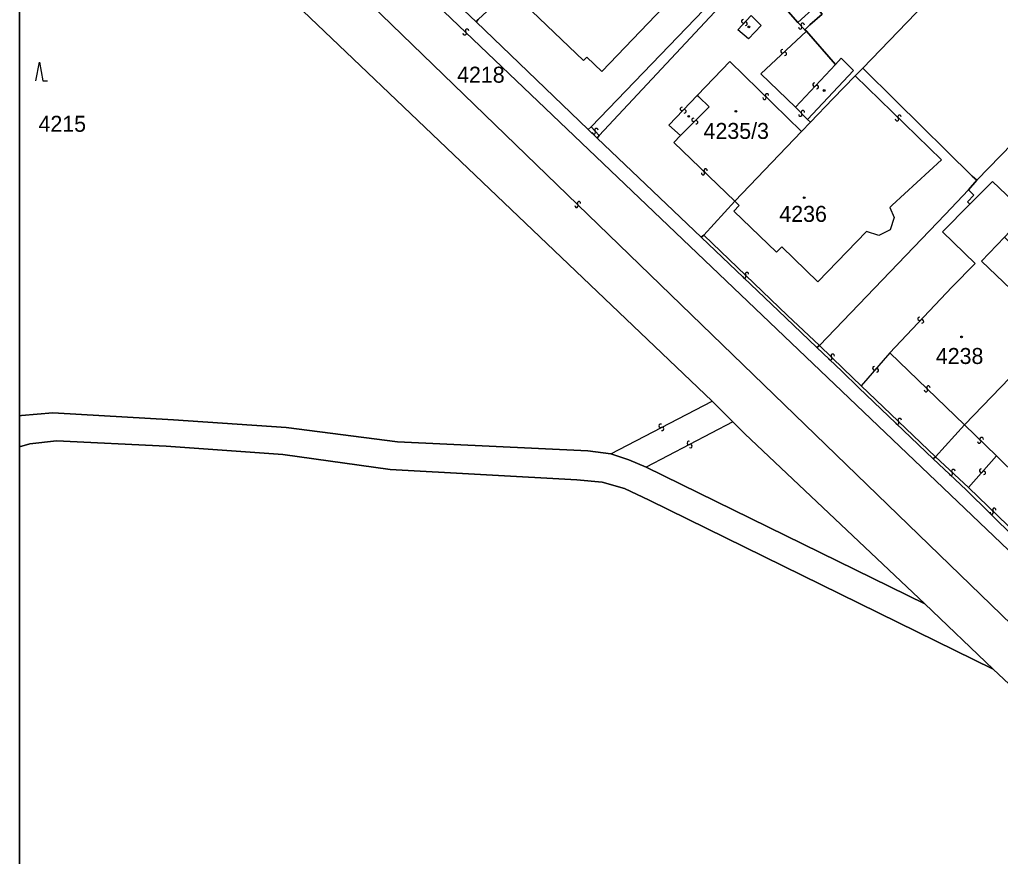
# Model space of a CAD drawing. Extents: x -598233 to -596890, y -1157848 to -1156431.
# Drawn here: x -598232.9 to -598128.6, y -1157143.3 to -1157054.3 of the extents above; entities that cross this region are included whole.
import ezdxf

# ---------------------------------------------------------------- set-up
doc = ezdxf.new("R2010")
doc.units = 0
for name, color, linetype in [('Level 1', 7, 'Continuous'), ('Level 13', 7, 'Continuous'), ('Level 3', 7, 'Continuous'), ('Level 4', 7, 'Continuous'), ('Level 5', 7, 'Continuous'), ('Level 60', 7, 'Continuous'), ('Vrstva 60', 7, 'Continuous'), ('zajmove_uzemi', 7, 'Continuous')]:
    doc.layers.add(name, color=color, linetype=linetype)

msp = doc.modelspace()

# ---------------------------------------------------------------- linework, layer by layer
at = {"layer": 'Level 1'}
for points in [[(-598159.23, -1157094.89), (-598230.25, -1157027.16), (-598232.89, -1157024.65)], [(-598184.32, -1157054.57), (-598196.28, -1157043.23)], [(-598172.99, -1157043.08), (-598163.59, -1157052.11), (-598170.97, -1157059.83), (-598172.56, -1157058.3), (-598172.9, -1157058.67), (-598180.74, -1157051.17)], [(-598129.11, -1157044.84), (-598143.19, -1157059.48)], [(-598107.13, -1157046.77), (-598131.06, -1157071.39)], [(-598155.51, -1157048.45), (-598172.08, -1157065.74)], [(-598154.89, -1157049.13), (-598171.23, -1157066.64)], [(-598150.09, -1157054.63), (-598154.89, -1157049.13)], [(-598149.35, -1157055.4), (-598148.81, -1157054.88), (-598147.53, -1157053.73), (-598148.21, -1157052.92), (-598150.09, -1157054.63)], [(-598184.11, -1157054.32), (-598184.32, -1157054.57)], [(-598172.39, -1157066), (-598184.32, -1157054.57)], [(-598149.19, -1157055.54), (-598149.35, -1157055.4)], [(-598146.08, -1157059.09), (-598149.19, -1157055.54)], [(-598149.06, -1157064.95), (-598144.17, -1157059.74), (-598145.5, -1157058.41), (-598146.08, -1157059.09)], [(-598143.19, -1157059.48), (-598144, -1157060.31)], [(-598143.19, -1157059.48), (-598139.69, -1157062.97), (-598131.54, -1157070.98), (-598131.06, -1157071.39)], [(-598148.77, -1157065.24), (-598146.37, -1157062.73), (-598144, -1157060.31)], [(-598148.77, -1157065.24), (-598149.73, -1157066.23)], [(-598148.77, -1157065.24), (-598149.06, -1157064.95)], [(-598172.08, -1157065.74), (-598172.39, -1157066)], [(-598171.46, -1157066.92), (-598172.39, -1157066)], [(-598149.73, -1157066.23), (-598156.81, -1157073.62)], [(-598171.23, -1157066.64), (-598171.46, -1157066.92)], [(-598160.37, -1157077.44), (-598171.46, -1157066.92)], [(-598131.06, -1157071.39), (-598131.93, -1157072.42)], [(-598131.8, -1157073.95), (-598129.39, -1157071.53), (-598125.76, -1157074.99), (-598128.13, -1157077.46)], [(-598131.93, -1157072.42), (-598134.44, -1157075.06), (-598147.81, -1157088.96)], [(-598131.93, -1157072.42), (-598131.37, -1157072.98), (-598132.05, -1157073.71), (-598131.8, -1157073.95)], [(-598156.81, -1157073.62), (-598160.11, -1157077.23)], [(-598160.11, -1157077.23), (-598160.37, -1157077.44)], [(-598148.09, -1157089.2), (-598151.37, -1157086.03), (-598160.37, -1157077.44)], [(-598147.81, -1157088.96), (-598148.09, -1157089.2)], [(-598135.7, -1157101.01), (-598143.6, -1157093.49), (-598145.41, -1157091.7), (-598148.09, -1157089.2)], [(-598124.02, -1157088.71), (-598125.63, -1157090.43), (-598132.37, -1157097.41)], [(-598159.23, -1157094.89), (-598157.01, -1157097.09)], [(-598232.89, -1157096.47), (-598232.68, -1157096.41), (-598229.34, -1157096.14), (-598216.51, -1157096.87), (-598204.52, -1157097.68), (-598192.69, -1157099.2), (-598172.45, -1157100.17), (-598170, -1157100.48)], [(-598157.01, -1157097.09), (-598155.74, -1157098.35), (-598136.59, -1157116.46)], [(-598132.37, -1157097.41), (-598135.45, -1157100.82)], [(-598232.89, -1157099.76), (-598231.79, -1157099.44), (-598228.95, -1157099.11), (-598217.31, -1157099.69), (-598204.89, -1157100.55), (-598193.47, -1157102.17), (-598173.62, -1157103.25), (-598170.91, -1157103.51), (-598168.54, -1157104.19), (-598165.93, -1157105.41), (-598129.31, -1157123.39)], [(-598170, -1157100.48), (-598168.09, -1157101.12), (-598166.23, -1157101.91)], [(-598135.45, -1157100.82), (-598135.7, -1157101.01)], [(-598127.04, -1157109.38), (-598132.19, -1157104.33), (-598135.7, -1157101.01)], [(-598166.23, -1157101.91), (-598136.59, -1157116.46)], [(-598136.59, -1157116.46), (-598129.31, -1157123.39)], [(-598129.31, -1157123.39), (-598117.4, -1157134.54)]]:
    msp.add_lwpolyline(points, dxfattribs=at)
at = {"layer": 'Level 13'}
for centre, start, end in [((-598155.91, -1157054.51), 84.726, 316.824), ((-598155.65, -1157054.77), 264.5116, 137.1016), ((-598149.59, -1157054.89), 351.2346, 223.3326), ((-598185.55, -1157055.77), 173.7072, 45.8052), ((-598185.29, -1157055.51), 353.4927, 226.0827), ((-598149.85, -1157055.15), 171.0201, 43.6101), ((-598151.74, -1157057.69), 80.4521, 313.0421), ((-598151.48, -1157057.96), 260.6666, 132.7646), ((-598148.34, -1157061.24), 84.2581, 316.3561), ((-598153.39, -1157062.38), 352.9445, 225.0425), ((-598148.08, -1157061.5), 264.0436, 136.6336), ((-598153.65, -1157062.64), 172.7301, 45.3201), ((-598162.43, -1157063.82), 83.381, 315.479), ((-598162.17, -1157064.08), 263.1666, 135.7566), ((-598149.83, -1157064.43), 171.7091, 43.8071), ((-598149.57, -1157064.17), 351.4946, 224.0847), ((-598161.19, -1157064.98), 82.3727, 314.4707), ((-598160.93, -1157065.24), 262.1583, 134.7483), ((-598139.55, -1157064.9), 172.95, 45.54), ((-598139.29, -1157064.64), 353.1645, 225.2625), ((-598171.8, -1157066.32), 170.7362, 42.8342), ((-598171.53, -1157066.06), 350.5217, 223.1117), ((-598160.18, -1157070.64), 173.4554, 45.5534), ((-598159.92, -1157070.38), 353.2409, 225.8309), ((-598173.39, -1157073.85), 353.311, 225.409), ((-598173.65, -1157074.11), 173.0966, 45.6866), ((-598155.78, -1157081.63), 173.4051, 45.9951), ((-598155.52, -1157081.37), 353.6195, 225.7175), ((-598137.15, -1157086.14), 83.9779, 316.0759), ((-598136.89, -1157086.4), 263.7635, 136.3535), ((-598146.65, -1157090.34), 172.9462, 45.5362), ((-598146.39, -1157090.08), 353.1606, 225.2586), ((-598141.97, -1157091.39), 86.3432, 318.9332), ((-598141.69, -1157091.63), 266.5577, 138.6556), ((-598136.21, -1157093.45), 353.1866, 225.7766), ((-598136.47, -1157093.71), 173.401, 45.499), ((-598164.7, -1157097.52), 64.8036, 296.9016), ((-598164.54, -1157097.84), 244.5891, 117.1791), ((-598139.53, -1157097.17), 173.456, 46.046), ((-598139.27, -1157096.91), 353.6705, 225.7685), ((-598161.7, -1157099.34), 64.7578, 297.3478), ((-598161.54, -1157099.66), 244.9722, 117.0702), ((-598130.81, -1157099.19), 173.0568, 45.1548), ((-598130.55, -1157098.93), 352.8424, 225.4324), ((-598133.82, -1157102.59), 174.4813, 46.5793), ((-598133.56, -1157102.33), 354.2669, 226.8569), ((-598130.6, -1157102.28), 86.1748, 318.2728), ((-598130.32, -1157102.52), 265.9603, 138.5503), ((-598129.47, -1157106.72), 173.3857, 45.4837), ((-598129.21, -1157106.46), 353.1713, 225.7613)]:
    msp.add_arc(centre, 0.184, start, end, dxfattribs=at)
at = {"layer": 'Level 3'}
msp.add_line((-598117.44, -1157120.53), (-598232.89, -1157010.34), dxfattribs=at)
for points in [[(-598232.89, -1157017.3), (-598226.27, -1157022.93), (-598120.77, -1157125.03), (-598117.44, -1157126.68)], [(-598155.34, -1157056.36), (-598156.48, -1157055.4), (-598155.08, -1157053.88), (-598154.02, -1157054.95), (-598155.34, -1157056.36)], [(-598150.09, -1157054.63), (-598149.35, -1157055.4)], [(-598149.19, -1157055.54), (-598154.03, -1157060.1), (-598150.34, -1157063.64)], [(-598160.77, -1157062.36), (-598157.32, -1157058.79), (-598149.73, -1157066.23)], [(-598150.34, -1157063.64), (-598146.08, -1157059.09)], [(-598144, -1157060.31), (-598134.83, -1157069.23), (-598140.06, -1157074.06), (-598140.31, -1157074.31), (-598139.84, -1157075.38), (-598140.28, -1157076.67), (-598141.48, -1157077.28), (-598142.79, -1157076.86), (-598147.99, -1157082.2), (-598151.81, -1157078.48), (-598152.38, -1157079.05), (-598156.9, -1157074.69), (-598156.34, -1157074.08), (-598156.81, -1157073.62)], [(-598162.59, -1157066.64), (-598163.84, -1157065.54), (-598160.77, -1157062.36)], [(-598162.59, -1157066.64), (-598159.53, -1157063.58), (-598160.64, -1157062.55), (-598160.77, -1157062.36)], [(-598149.06, -1157064.95), (-598150.34, -1157063.64)], [(-598171.23, -1157066.64), (-598172.08, -1157065.74)], [(-598156.81, -1157073.62), (-598163.28, -1157067.39), (-598162.59, -1157066.64)], [(-598140.31, -1157089.75), (-598133.72, -1157082.78), (-598131.23, -1157080.25), (-598134.72, -1157076.88), (-598131.8, -1157073.95)], [(-598160.11, -1157077.23), (-598151.19, -1157085.77), (-598147.81, -1157088.96)], [(-598122.79, -1157087.4), (-598130.58, -1157080.02), (-598128.13, -1157077.46)], [(-598147.81, -1157088.96), (-598145.23, -1157091.47), (-598143.35, -1157093.27)], [(-598140.31, -1157089.75), (-598143.35, -1157093.27)], [(-598132.37, -1157097.41), (-598140.31, -1157089.75)], [(-598143.35, -1157093.27), (-598135.45, -1157100.82)], [(-598170, -1157100.48), (-598159.23, -1157094.89)], [(-598117.55, -1157094.91), (-598122.09, -1157099.76), (-598122.77, -1157098.9), (-598126.59, -1157103.05), (-598128.98, -1157100.72)], [(-598157.01, -1157097.09), (-598166.23, -1157101.91)], [(-598128.98, -1157100.72), (-598132.37, -1157097.41)], [(-598131.93, -1157104.09), (-598135.45, -1157100.82)], [(-598131.93, -1157104.09), (-598128.98, -1157100.72)], [(-598126.75, -1157109.09), (-598131.93, -1157104.09)]]:
    msp.add_lwpolyline(points, dxfattribs=at)
at = {"layer": 'Level 5'}
msp.add_lwpolyline([(-598231.16, -1157060.85), (-598230.78, -1157058.85), (-598230.41, -1157060.85), (-598229.91, -1157060.85)], dxfattribs=at)
for centre, radius in [((-598155.31, -1157055.1), 0.09), ((-598155.31, -1157055.1), 0.0521), ((-598147.3, -1157061.86), 0.09), ((-598147.3, -1157061.86), 0.0521), ((-598156.69, -1157064.07), 0.09), ((-598156.69, -1157064.07), 0.0521), ((-598161.71, -1157064.61), 0.09), ((-598161.71, -1157064.61), 0.0521), ((-598149.42, -1157073.26), 0.09), ((-598149.42, -1157073.26), 0.0521), ((-598132.69, -1157088.06), 0.09), ((-598132.69, -1157088.06), 0.0521)]:
    msp.add_circle(centre, radius, dxfattribs=at)
at = {"layer": 'Level 60'}
for points in [[(-598170.52, -1157039.93), (-598175.51, -1157034.6), (-598176.86, -1157035.92), (-598178.45, -1157034.38), (-598178.73, -1157034.7), (-598179.5, -1157035.47), (-598181.82, -1157037.78), (-598183, -1157036.67), (-598186.42, -1157040.24), (-598185.27, -1157041.33), (-598187.95, -1157044.29), (-598180.74, -1157051.17), (-598184.11, -1157054.32), (-598184.32, -1157054.57), (-598196.28, -1157043.23), (-598196.05, -1157042.96), (-598180.92, -1157027.21), (-598179.15, -1157025.42), (-598173.93, -1157020.14), (-598164.13, -1157010.24), (-598153.32, -1157022.66), (-598162.98, -1157032.36), (-598164.84, -1157034.23), (-598167.89, -1157037.39)], [(-598138.82, -1157032.43), (-598154.89, -1157049.13), (-598171.23, -1157066.64), (-598171.46, -1157066.92), (-598172.39, -1157066), (-598172.08, -1157065.74), (-598155.51, -1157048.45), (-598153.3, -1157046.22), (-598151.44, -1157044.3), (-598133.54, -1157025.78), (-598128.72, -1157020.8), (-598124.4, -1157016.33), (-598115.98, -1157031.27), (-598129.11, -1157044.84)], [(-598143.19, -1157059.48), (-598129.11, -1157044.84), (-598115.98, -1157031.27), (-598109.57, -1157042.5), (-598107.13, -1157046.77), (-598131.06, -1157071.39), (-598131.54, -1157070.98), (-598139.69, -1157062.97)], [(-598154.89, -1157049.13), (-598138.82, -1157032.43), (-598129.11, -1157044.84), (-598143.19, -1157059.48), (-598144, -1157060.31), (-598146.37, -1157062.73), (-598148.77, -1157065.24), (-598149.06, -1157064.95), (-598144.17, -1157059.74), (-598145.5, -1157058.41), (-598146.08, -1157059.09), (-598149.19, -1157055.54), (-598149.35, -1157055.4), (-598148.81, -1157054.88), (-598147.53, -1157053.73), (-598148.21, -1157052.92), (-598150.09, -1157054.63)], [(-598184.11, -1157054.32), (-598180.74, -1157051.17), (-598172.9, -1157058.67), (-598172.56, -1157058.3), (-598170.97, -1157059.83), (-598163.59, -1157052.11), (-598172.99, -1157043.08), (-598170.74, -1157040.17), (-598170.52, -1157039.93), (-598167.89, -1157037.39), (-598164.84, -1157034.23), (-598161.43, -1157037.74), (-598156.32, -1157043.16), (-598155.48, -1157043.96), (-598153.3, -1157046.22), (-598155.51, -1157048.45), (-598172.08, -1157065.74), (-598172.39, -1157066), (-598184.32, -1157054.57)], [(-598180.74, -1157051.17), (-598172.99, -1157043.08), (-598163.59, -1157052.11), (-598170.97, -1157059.83), (-598172.56, -1157058.3), (-598172.9, -1157058.67)], [(-598131.93, -1157072.42), (-598131.06, -1157071.39), (-598107.13, -1157046.77), (-598106.45, -1157047.94), (-598098.39, -1157061.95), (-598101.09, -1157064.98), (-598105.4, -1157069.5), (-598120.39, -1157084.83), (-598121.14, -1157084.17), (-598121.86, -1157083.46), (-598128.13, -1157077.46), (-598125.76, -1157074.99), (-598129.39, -1157071.53), (-598131.8, -1157073.95), (-598132.05, -1157073.71), (-598131.37, -1157072.98)], [(-598149.06, -1157064.95), (-598148.77, -1157065.24), (-598149.73, -1157066.23), (-598156.81, -1157073.62), (-598160.11, -1157077.23), (-598160.37, -1157077.44), (-598171.46, -1157066.92), (-598171.23, -1157066.64), (-598154.89, -1157049.13), (-598150.09, -1157054.63), (-598148.21, -1157052.92), (-598147.53, -1157053.73), (-598148.81, -1157054.88), (-598149.35, -1157055.4), (-598149.19, -1157055.54), (-598146.08, -1157059.09), (-598145.5, -1157058.41), (-598144.17, -1157059.74)], [(-598148.77, -1157065.24), (-598146.37, -1157062.73), (-598144, -1157060.31), (-598143.19, -1157059.48), (-598139.69, -1157062.97), (-598131.54, -1157070.98), (-598131.06, -1157071.39), (-598131.93, -1157072.42), (-598134.44, -1157075.06), (-598147.81, -1157088.96), (-598148.09, -1157089.2), (-598151.37, -1157086.03), (-598160.37, -1157077.44), (-598160.11, -1157077.23), (-598156.81, -1157073.62), (-598149.73, -1157066.23)], [(-598134.44, -1157075.06), (-598131.93, -1157072.42), (-598131.37, -1157072.98), (-598132.05, -1157073.71), (-598131.8, -1157073.95), (-598129.39, -1157071.53), (-598125.76, -1157074.99), (-598128.13, -1157077.46), (-598121.86, -1157083.46), (-598121.14, -1157084.17), (-598120.39, -1157084.83), (-598120.83, -1157085.36), (-598121.73, -1157086.26), (-598122.79, -1157087.4), (-598124.02, -1157088.71), (-598125.63, -1157090.43), (-598132.37, -1157097.41), (-598135.45, -1157100.82), (-598135.7, -1157101.01), (-598143.6, -1157093.49), (-598145.41, -1157091.7), (-598148.09, -1157089.2), (-598147.81, -1157088.96)], [(-598121.73, -1157086.26), (-598120.83, -1157085.36), (-598119.23, -1157086.95), (-598114.31, -1157091.62), (-598116.02, -1157093.41), (-598115.04, -1157094.3), (-598113.88, -1157095.34), (-598123.68, -1157105.73), (-598126.75, -1157109.09), (-598127.04, -1157109.38), (-598132.19, -1157104.33), (-598135.7, -1157101.01), (-598135.45, -1157100.82), (-598132.37, -1157097.41), (-598125.63, -1157090.43), (-598124.02, -1157088.71), (-598122.79, -1157087.4)]]:
    msp.add_lwpolyline(points, close=True, dxfattribs=at)
at = {"layer": 'Vrstva 60'}
for points in [[(-598232.89, -1156430.86), (-598232.89, -1157835.58)], [(-598230.25, -1157027.16), (-598159.23, -1157094.89), (-598157.01, -1157097.09), (-598155.74, -1157098.35), (-598136.59, -1157116.46), (-598129.31, -1157123.39), (-598117.4, -1157134.54), (-598117.42, -1157133.54), (-598117.44, -1157130.35), (-598117.44, -1157118.61), (-598127.04, -1157109.38), (-598132.19, -1157104.33), (-598135.7, -1157101.01), (-598143.6, -1157093.49), (-598145.41, -1157091.7), (-598148.09, -1157089.2), (-598151.37, -1157086.03), (-598160.37, -1157077.44), (-598171.46, -1157066.92), (-598172.39, -1157066), (-598184.32, -1157054.57), (-598196.28, -1157043.23)], [(-598009.87, -1157147.41), (-598011.65, -1157136.39), (-598017.09, -1157116.49), (-598022.5, -1157094.64), (-598023.35, -1157090.35), (-598117.4, -1157134.54), (-598129.31, -1157123.39), (-598165.93, -1157105.41), (-598168.54, -1157104.19), (-598170.91, -1157103.51), (-598173.62, -1157103.25), (-598193.47, -1157102.17), (-598204.89, -1157100.55), (-598217.31, -1157099.69), (-598228.95, -1157099.11), (-598231.79, -1157099.44), (-598232.89, -1157099.76), (-598232.89, -1157171.98)]]:
    msp.add_lwpolyline(points, dxfattribs=at)
for points in [[(-598232.89, -1157024.65), (-598232.89, -1157096.47), (-598232.68, -1157096.41), (-598229.34, -1157096.14), (-598216.51, -1157096.87), (-598204.52, -1157097.68), (-598192.69, -1157099.2), (-598172.45, -1157100.17), (-598170, -1157100.48), (-598168.09, -1157101.12), (-598166.23, -1157101.91), (-598136.59, -1157116.46), (-598155.74, -1157098.35), (-598157.01, -1157097.09), (-598159.23, -1157094.89), (-598230.25, -1157027.16)], [(-598232.89, -1157096.47), (-598232.89, -1157099.76), (-598231.79, -1157099.44), (-598228.95, -1157099.11), (-598217.31, -1157099.69), (-598204.89, -1157100.55), (-598193.47, -1157102.17), (-598173.62, -1157103.25), (-598170.91, -1157103.51), (-598168.54, -1157104.19), (-598165.93, -1157105.41), (-598129.31, -1157123.39), (-598136.59, -1157116.46), (-598166.23, -1157101.91), (-598168.09, -1157101.12), (-598170, -1157100.48), (-598172.45, -1157100.17), (-598192.69, -1157099.2), (-598204.52, -1157097.68), (-598216.51, -1157096.87), (-598229.34, -1157096.14), (-598232.68, -1157096.41)]]:
    msp.add_lwpolyline(points, close=True, dxfattribs=at)
at = {"layer": 'zajmove_uzemi'}
msp.add_lwpolyline([(-598232.89, -1156430.86), (-596890.46, -1156430.86), (-596890.46, -1157848.46), (-598232.89, -1157848.46)], close=True, dxfattribs=at)

# ---------------------------------------------------------------- texts
at = {"layer": 'Level 4'}
for s, p in [('4218', (-598186.35, -1157061.03)), ('4215', (-598230.88, -1157066.25)), ('4235/3', (-598160.13, -1157067.01)), ('4236', (-598152.07, -1157075.83)), ('4238', (-598135.42, -1157090.94))]:
    msp.add_text(s, height=1.7, dxfattribs=at).set_placement(p)

doc.saveas('drawing.dxf')
